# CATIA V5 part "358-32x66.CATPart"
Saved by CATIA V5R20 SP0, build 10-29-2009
Part number: 358-32X66
Definition: NONE
Nomenclature: 358-32X66
Source: Unknown
Description: 358-32X66
Bounding box of the stored display mesh (mm): x -17 to 49, y -22.5 to 22.5, z -22.5 to 22.5
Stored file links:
  C:\Users\Utente\Desktop\IO LAVORO\3D X SITO CF\X SITO\PLASTICA\358\358-32x66.CATPart

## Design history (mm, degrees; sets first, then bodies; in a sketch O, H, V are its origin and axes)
Body1 "358-32X66" (main body)
  Solid1: solid without history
